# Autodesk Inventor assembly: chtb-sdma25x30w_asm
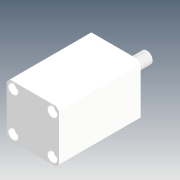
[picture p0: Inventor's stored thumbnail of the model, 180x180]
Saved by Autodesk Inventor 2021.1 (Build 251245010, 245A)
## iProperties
Company: Microsoft
Created: 2018-05
Part Number: chtb-sdma25x30w_asm
Description: STEP AP214
Document SubType Name: Assembly
Designer: user
Title: chtb-sdma25x30w_asm.STEP
Author: Windows
Revision Number: ÈÎºÎ
Sending System: SolidWorks 2015
Preprocessor: SwSTEP 2.0
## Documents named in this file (4)
- D:\Vault_2016\Projekty\Clamptek\Hydraulic\CHTB\CHTB-25\Inventor\chtb-sdma25x30w\chtb-sdma25x30w_asm.iam
- D:\Vault_2016\Projekty\Clamptek\Hydraulic\CHTB\CHTB-25\Inventor\chtb-sdma25x30w\CHTB-25QG.ipt
- D:\Vault_2016\Projekty\Clamptek\Hydraulic\CHTB\CHTB-25\Inventor\chtb-sdma25x30w\CHTB-SDMA25X30NBT.ipt
- D:\Vault_2016\Projekty\Clamptek\Hydraulic\CHTB\CHTB-25\Inventor\chtb-sdma25x30w\CHTB-SDMA25X30WHSG.ipt
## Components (3 placed, 3 different names)
1. CHTB-25QG_1
2. CHTB-SDMA25X30NBT_2
3. CHTB-SDMA25X30WHSG_3
